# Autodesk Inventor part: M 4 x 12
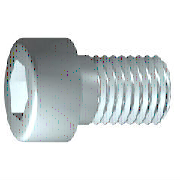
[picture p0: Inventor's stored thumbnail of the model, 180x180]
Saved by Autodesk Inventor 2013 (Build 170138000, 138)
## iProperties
IsCustomPart: 1
Company: 한국ATC센터
Created: 2009-02
Part Number: M 4 x 12
Material: 강철, 연강
Description: 6각머리 태핑 나사
Document SubType Name: Modeling
Standard: KS B 1003
Designer: KYOUNG IL JANG
Standards Organization: KS
Language: ko-KR
Size Designation: M 4 x 12
Categories: <MemberInstance><Categories><Category DisplayName="조임쇠" InternalName="e4da775c-781d-43d5-af7c-5136215cf5a6" Mnemonic="FSTN"><Category DisplayName="볼트" InternalN
Density: 7.86 g/cm^3
Mass: 2.03818 g
Surface Area: 3.05968 cm^2
Volume: 0.259311 cm^3
Vendor: CBT Solutions
Author: KYOUNG IL JANG
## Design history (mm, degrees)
sketch "스케치1"
  geometry: L1 (-1, 0)-(12, 0); L2 (12, 0)-(12, 2); L3 (12, 2)-(1.75, 2); L4 (1.75, 2)-(1.32, 2); L5 (1.32, 2)-(0, 2); L6 (0, 2)-(0, 3.5); L7 (0, 3.5)-(-4, 3.5); L8 (-4, 3.5)-(-4, 1.732); L9 (-4, 1.732)-(-2, 1.732); L10 (-2, 1.732)-(-1, 0); L11 (-7.2, 0)-(15.2, 0) reference; L12 (0, -0.7)-(0, 4.2) reference; L13 (1.75, 2)-(0, 2)
  constraints: 22 end point, 6 parallel, 2 collinear, 2 perpendicular, 1 horizontal, 1 point on line
  dimensions: "d1" = 10.25 distance from line of L3.end L2 (= GEL); "d2" = 0.42952 distance of L4.end L3.end (computed from GAL); "d3" = 4 distance between parallel lines of L8 L6 (= KOH); "d4" = 2 distance of L8.end L9.end (= INTI); "d5" = 60 deg angle of L10 L1; "d6" = 4 diameter of L3 L1 (= GD); "d7" = 4 diameter of L5 L1 (= BDM); "d8" = 3.4641 diameter of L9 L1 (= 1.1547 x SW); "d9" = 7 diameter of L7 L1 (= KOD); "d26" = 12 distance between parallel lines of L12 L2 (= NLG)
revolve "본체" sketch "스케치1" stored, may be unused: angle "d10" = 90 deg
sketch "스케치2"
  geometry: L1 (0, -4.9)-(0, 4.9) reference; L2 (-4.9, 0)-(4.9, 0) reference; L3 (1.732, 0)-(0.866, -1.5); L4 (0.866, -1.5)-(-0.866, -1.5); L5 (-0.866, -1.5)-(-1.732, 0); L6 (-1.732, 0)-(-0.866, 1.5); L7 (-0.866, 1.5)-(0.866, 1.5); L8 (0.866, 1.5)-(1.732, 0); 2 further points
  constraints: 12 end point, 1 coincident, 1 horizontal alignment, 1 point on line, 12 other
extrude "슬롯" join sketch "스케치2" stored distance "d11" = 10; taper "d12" = 0 deg
workplane "Work Plane1"
fillet "Fillet2" dims "d30" = 0.1 (= R)
sketch "스케치4"
  geometry: C1 r 2.574 at (0, 0); 1 further point
  constraints: 1 centre point, 1 coincident
extrude "돌출3" cut sketch "스케치4" distance "d31" = 2; taper "d32" = 0 deg
chamfer "모따기3" distance "d33" = 0.4; stored, may be unused: second distance "d34" = 2, angle "d35" = 45 deg
body "Solid1"
fillet "모깎기1" dims "d17" = 0.4 (= RR)
feature "스레드" dims "d13" = 10.25 (= GEL), "d14" = 0
chamfer "모따기1" distance "d15" = 0.42941 (= -0.5 x SPD + 0.5 x GD); stored, may be unused: second distance "d16" = 0.42941 (= GUL), angle "d27" = 45 deg
other parameters: "GD" = 4 (= NND) [user parameter; used in 2 equation terms], "NLG" = 12 [user parameter; used in 1 equation term], "GEL" = 10.25 [user parameter; used in 2 equation terms], "KOD" = 7 [user parameter; used in 1 equation term], "KOH" = 4 [user parameter; used in 1 equation term], "INTI" = 2 [user parameter; used in 1 equation term], "GAL" = 0.42941 (= 0.61345 x PTC) [user parameter; used in 1 equation term], "GUL" = 0.42941 (= 0.61345 x PTC) [user parameter; used in 1 equation term], "BDM" = 4 (= NND) [user parameter; used in 1 equation term], "SW" = 3 [user parameter; used in 2 equation terms], "RR" = 0.4 [user parameter; used in 1 equation term], "SPD" = 3.14117 (= NND - 1.2269 x PTC) [user parameter; used in 1 equation term], "d19" = 0, "d28" = 0, "d29" = 0, "R" = 0.1 [user parameter; used in 1 equation term], "PHH" = 0.2 [user parameter], "GD1" = 3.14117 (= THREADDIA - 1.2269 x PTC) [user parameter], "THREADDIA" = 4 [user parameter; used in 1 equation term], "FAWI" = 45 deg [user parameter], "TPU" = 14.28571 (computed from PTC) [user parameter], "PTC" = 0.7 [user parameter; used in 5 equation terms], "NND" = 4 [user parameter; used in 3 equation terms], "TOA" = 30 deg [user parameter], "E0" = 3.465 (= 1.155 x SW) [user parameter]
